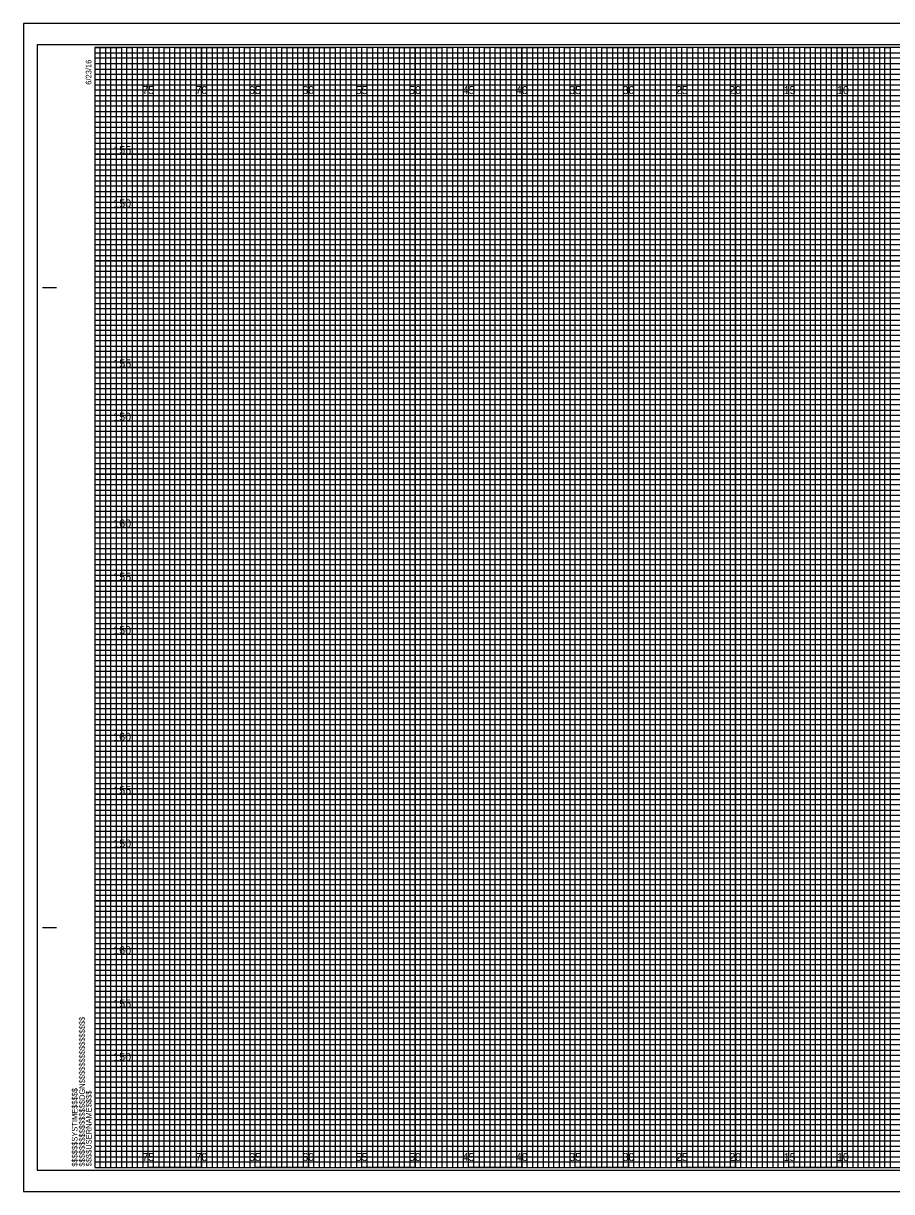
# Model space of a CAD drawing. Extents: x -7 to 162, y 108 to 217.
# Drawn here: x -6.7 to 74.6, y 107.7 to 217.2 of the extents above; entities that cross this region are included whole.
import ezdxf

# ---------------------------------------------------------------- set-up
doc = ezdxf.new("R2010")
doc.units = 0
for name, color, linetype in [('Exist CMT Pavement', 7, 'Continuous'), ('Prop CMT Pvmt Course 1 Wedge', 7, 'Continuous'), ('Prop CMT Pvmt Course 2 Wedge', 7, 'Continuous'), ('Prop CMT Pvmt Course 3 Wedge', 7, 'Continuous'), ('Prop CMT Pvmt Wedge Surface 1', 7, 'Continuous'), ('Prop CMT Pvmt Wedge Surface 2', 7, 'Continuous'), ('Prop CMT Shear Line', 7, 'Continuous'), ('Prop VPT Ditch Grade Left Label', 7, 'Continuous'), ('Prop XS Elevation Labels', 7, 'Continuous'), ('Scratch_Level_3', 7, 'Continuous'), ('Scratch_Level_5', 7, 'Continuous')]:
    doc.layers.add(name, color=color, linetype=linetype)

msp = doc.modelspace()

# ---------------------------------------------------------------- linework, layer by layer
at = {"layer": 'Exist CMT Pavement'}
for p, q in [((0, 214.5), (130, 214.5)), ((130, 213.99), (0, 213.99)), ((0, 213.99), (0, 213.5)), ((0, 213.5), (130, 213.5)), ((130, 212.94), (0, 212.94)), ((0, 212.94), (0, 212)), ((0, 212), (160, 212))]:
    msp.add_line(p, q, dxfattribs=at)
for points in [[(0, 211.5), (135, 211.5), (160, 211.5), (160, 211), (0, 211)], [(0, 210.5), (160, 210.5), (160, 209.5), (0, 209.5)], [(0, 209), (160, 209), (160, 208.5), (0, 208.49)], [(0, 208), (160, 208), (160, 207), (0, 207)], [(0, 206.5), (160, 206.5), (160, 206), (0, 206)], [(0, 205.5), (160, 205.5), (160, 204.5), (0, 204.5)], [(0, 204), (160, 204), (160, 203.5), (0, 203.5)], [(0, 203), (160, 203), (160, 202), (0, 202)], [(0, 201.5), (160, 201.5), (160, 201), (0, 201)], [(0, 200.5), (160, 200.5), (160, 199.5), (0, 199.5)], [(0, 199), (160, 199), (160, 198.5), (0, 198.5)], [(0, 198), (160, 198), (160, 196.97), (160, 196.5), (160, 196), (0, 196)], [(0, 197), (160, 197), (160, 196.5), (0, 196.5)], [(0, 195.5), (160, 195.5), (160, 194.5), (0, 194.52)], [(0, 194.52), (160, 194.5), (160, 194), (0, 194)], [(0, 193.5), (160, 193.5), (160, 193), (0, 193)], [(0, 192), (160, 192), (160, 191.5), (0, 191.5)], [(0, 191), (160, 191), (160, 190.5), (0, 190.5)], [(-0.04, 189.44), (160, 189.44), (160, 188.94), (-0.04, 188.94)], [(0, 188.5), (160, 188.5), (160, 188), (0, 188)], [(0, 187), (160, 187), (160, 186.5), (0, 186.5)], [(0, 186), (160, 186), (160, 185.5), (0, 185.5)], [(0, 184.5), (160, 184.5), (160, 184), (0, 184)], [(0, 183.5), (160, 183.5), (160, 183), (0, 183)], [(0, 182), (160, 182), (160, 181.5), (0, 181.5)], [(0, 181), (160, 181), (160, 180.5), (0, 180.5)], [(0, 179.5), (160, 179.5), (160, 178.99), (0, 179)], [(0, 178.5), (160, 178.5), (160, 178), (0, 178)], [(0, 177), (160, 177), (160, 176.5), (0, 176.5)], [(0, 176), (160, 176), (160, 175.5), (0, 175.5)], [(0, 174.5), (160, 174.5), (160, 174), (0, 174)], [(0, 173.5), (160, 173.5), (160, 173), (0, 173)], [(0, 172), (160, 172), (160, 171.5), (0, 171.5)], [(0, 171), (160, 171), (160, 170.5), (0, 170.5)], [(0, 169.5), (160, 169.5), (160, 169), (0, 169)], [(0, 168.5), (160.03, 168.46), (160, 168), (0, 168)], [(0, 167), (160, 167), (160, 166.5), (0, 166.5)], [(0, 166), (160, 166), (160, 165.5), (0, 165.5)], [(0, 164.5), (160, 164.5), (160, 164), (0, 164)], [(0, 163.5), (160, 163.5), (160, 163), (0, 163)], [(0, 162), (160, 162), (160, 161.5), (0, 161.5)], [(0, 161), (160, 161), (160, 160.5), (0, 160.5)], [(0, 159.5), (160, 159.5), (160, 159), (0, 159)], [(0, 158.5), (160, 158.5), (160, 158), (0, 158)], [(0, 157), (160, 157), (160, 156.5), (0, 156.5)], [(0, 156), (160, 156), (160, 155.5), (0, 155.5)], [(0, 154.5), (160, 154.5), (160, 154), (0, 154)], [(0, 153.5), (160, 153.5), (160, 153), (0, 153)], [(0, 152), (160, 152), (160, 151.5), (0, 151.5)], [(0, 151), (160, 151), (160, 150.5), (0, 150.5)], [(0, 149.5), (160, 149.5), (160, 148.99), (0, 149)], [(0, 148.5), (160, 148.5), (160, 148), (0, 148)], [(0, 147), (160, 147), (160, 146.5), (0, 146.5)], [(0, 146), (160, 146), (160, 145.5), (0, 145.5)], [(0, 144.5), (160, 144.5), (160, 144), (0, 144)], [(0, 143.5), (160, 143.5), (160, 143), (0, 143)], [(0, 142), (160, 142), (160, 141.5), (0, 141.5)], [(0, 141), (160, 141), (160, 140.5), (0, 140.5)], [(0, 139.5), (160, 139.5), (160, 139), (0, 139)], [(0, 138.5), (160.03, 138.46), (160, 138), (0, 138)], [(0, 137), (160, 137), (160, 136.5), (0, 136.5)], [(0, 136), (160, 136), (160, 135.5), (0, 135.5)], [(0, 134.5), (160, 134.5), (160, 134), (0, 134)], [(0, 133.5), (160, 133.5), (160, 133), (0, 133)], [(0, 132), (160, 132), (160, 131.5), (0, 131.5)], [(0, 131), (160, 131), (160, 130.5), (0, 130.5)], [(0, 129.5), (160, 129.5), (160, 129), (0, 129)], [(0, 128.5), (160, 128.5), (160, 128), (0, 128)], [(0, 127), (160, 127), (160, 126.5), (0, 126.5)], [(0, 126), (160, 126), (160, 125.5), (0, 125.5)], [(0, 124.5), (160, 124.5), (160, 124), (0, 124)], [(0, 123.5), (160, 123.5), (160, 123), (0, 123)], [(0, 122), (160, 122), (160, 121.5), (0, 121.5)], [(0, 121), (160, 121), (160, 120.5), (0, 120.5)], [(0, 119.5), (160, 119.5), (160, 119), (0, 119)], [(0, 118.5), (160, 118.5), (160, 118), (0, 118)], [(0, 117), (160, 117), (160, 116.5), (0, 116.5)], [(0, 116), (160, 116), (160, 115.5), (0, 115.5)], [(0, 114.5), (160, 114.5), (160, 114), (0, 114)], [(0, 113.5), (160, 113.5), (160, 113), (0, 113)], [(0, 112), (160, 112), (160, 111.5), (0, 111.5)], [(0, 111), (160, 111), (160, 110.5), (0, 110.5)]]:
    msp.add_lwpolyline(points, dxfattribs=at)
at = {"layer": 'Prop CMT Pvmt Course 2 Wedge'}
for p, q in [((5, 215), (0, 215)), ((5, 110), (5, 215)), ((15, 215), (10, 215)), ((10, 215), (10, 110)), ((15, 110), (15, 215)), ((25, 215), (20, 215)), ((20, 215), (20, 110)), ((25, 110), (25, 215)), ((35, 215), (30, 215)), ((30, 215), (30, 110)), ((35, 110), (35, 215)), ((45, 215), (40, 215)), ((40, 215), (40, 110)), ((45, 110), (45, 215)), ((55, 215), (50, 215)), ((50, 215), (50, 110)), ((55, 110), (55, 215)), ((65, 215), (60, 215)), ((60, 215), (60, 110)), ((65, 110), (65, 215)), ((75, 215), (70, 215)), ((70, 215), (70, 110)), ((10, 110), (5, 110)), ((20, 110), (15, 110)), ((30, 110), (25, 110)), ((40, 110), (35, 110)), ((50, 110), (45, 110)), ((60, 110), (55, 110)), ((70, 110), (65, 110))]:
    msp.add_line(p, q, dxfattribs=at)
for points in [[(0, 210), (160, 210), (160, 205), (0, 205)], [(0, 200), (160, 200), (160, 195), (0, 195)], [(0, 190), (160, 190), (160, 185), (0, 185)], [(0, 180), (160, 180), (160, 175), (0, 175)], [(0, 170), (160, 170), (160, 165), (0, 165)], [(0, 160), (160, 160), (160, 155), (0, 155)], [(0, 150), (160, 150), (160, 145), (0, 145)], [(0, 140), (160, 140), (160, 135), (0, 135)], [(0, 130), (160, 130), (160, 125), (0, 125)], [(0, 120), (160, 120), (160, 115), (0, 115)]]:
    msp.add_lwpolyline(points, dxfattribs=at)
at = {"layer": 'Prop CMT Pvmt Course 3 Wedge'}
for points in [[(0, 215), (2.5, 215), (2.5, 110), (7.5, 110), (7.5, 215), (12.5, 215), (12.5, 110), (17.5, 110), (17.5, 215), (22.5, 215), (22.5, 110), (27.5, 110), (27.5, 215), (32.5, 215), (32.5, 110), (37.5, 110), (37.5, 215), (42.5, 215), (42.5, 110), (47.5, 110), (47.5, 215), (52.5, 215), (52.5, 110), (57.5, 110), (57.5, 215), (62.5, 215), (62.5, 110), (67.5, 110), (67.5, 215), (72.5, 215), (72.5, 110), (77.5, 110)], [(0, 212.5), (137.5, 212.5)], [(0, 202.5), (160, 202.5), (160, 207.5), (0, 207.5)], [(0, 192.5), (160, 192.5), (160, 197.5), (0, 197.5)], [(0, 182.5), (160, 182.5), (160, 187.5), (0, 187.5)], [(0, 172.5), (160, 172.5), (160, 177.5), (0, 177.5)], [(0, 162.5), (160, 162.5), (160, 167.5), (0, 167.5)], [(0, 152.5), (160, 152.5), (160, 157.5), (0, 157.5)], [(0, 142.5), (160, 142.5), (160, 147.5), (0, 147.5)], [(0, 132.5), (160, 132.5), (160, 137.5), (0, 137.5)], [(0, 122.5), (160, 122.5), (160, 127.5), (0, 127.5)], [(0, 112.5), (160, 112.5), (160, 117.5), (0, 117.5)]]:
    msp.add_lwpolyline(points, dxfattribs=at)
at = {"layer": 'Prop CMT Pvmt Wedge Surface 1'}
for p, q in [((-4.9, 192.5), (-3.65, 192.5)), ((-4.85, 192.5), (-3.6, 192.5)), ((-4.9, 132.5), (-3.65, 132.5)), ((-4.85, 132.5), (-3.6, 132.5)), ((0, 110), (0, 110)), ((0, 110), (0, 110)), ((0, 110), (0, 110)), ((0, 110), (0, 110)), ((0, 110), (0, 110)), ((0, 110), (0, 110)), ((0, 110), (0, 110))]:
    msp.add_line(p, q, dxfattribs=at)
msp.add_lwpolyline([(160, 215), (0, 215), (0, 110), (160, 110)], close=True, dxfattribs=at)
at = {"layer": 'Prop CMT Pvmt Wedge Surface 2'}
for points in [[(0, 110), (0.5, 110), (0.5, 215), (1, 215), (1, 110)], [(1, 110), (1.5, 110), (1.5, 215), (2, 215), (2, 110)], [(2.5, 110), (3, 110), (3, 215), (3.5, 215), (3.5, 110)], [(3.5, 110), (4, 110), (4, 215), (4.5, 215), (4.5, 110)], [(5, 110), (5.5, 110), (5.5, 215), (6, 215), (6, 110)], [(6, 110), (6.5, 110), (6.5, 215), (7, 215), (7, 110)], [(7.5, 110), (8, 110), (8, 215), (8.5, 215), (8.5, 110)], [(8.5, 110), (9, 110), (9, 215), (9.5, 215), (9.5, 110)], [(10, 110), (10.5, 110), (10.5, 215), (11, 215), (11, 110)], [(11, 110), (11.5, 110), (11.5, 215), (12, 215), (12, 110)], [(12.5, 110), (13, 110), (13, 215), (13.5, 215), (13.5, 110)], [(13.5, 110), (14, 110), (14, 215), (14.5, 215), (14.5, 110)], [(15, 110), (15.5, 110), (15.5, 215), (16, 215), (16, 110)], [(16, 110), (16.5, 110), (16.5, 215), (17, 215), (17, 110)], [(17.5, 110), (18, 110), (18, 215), (18.5, 215), (18.5, 110)], [(18.5, 110), (19, 110), (19, 215), (19.5, 215), (19.5, 110)], [(20, 110), (20.5, 110), (20.5, 215), (21, 215), (21, 110)], [(21, 110), (21.5, 110), (21.5, 215), (22, 215), (22, 110)], [(22.5, 110), (23, 110), (23, 215), (23.5, 215), (23.5, 110)], [(23.5, 110), (24, 110), (24, 215), (24.5, 215), (24.5, 110)], [(25, 110), (25.5, 110), (25.5, 215), (26, 215), (26, 110)], [(26, 110), (26.5, 110), (26.5, 215), (27, 215), (27, 110)], [(27.5, 110), (28, 110), (28, 215), (28.5, 215), (28.5, 110)], [(28.5, 110), (29, 110), (29, 215), (29.5, 215), (29.5, 110)], [(30, 110), (30.5, 110), (30.5, 215), (31, 215), (31, 110)], [(31, 110), (31.5, 110), (31.5, 215), (32, 215), (32, 110)], [(32.5, 110), (33, 110), (33, 215), (33.5, 215), (33.5, 110)], [(33.5, 110), (34, 110), (34, 215), (34.5, 215), (34.5, 110)], [(35, 110), (35.5, 110), (35.5, 215), (36, 215), (36, 110)], [(36, 110), (36.5, 110), (36.5, 215), (37, 215), (37, 110)], [(37.5, 110), (38, 110), (38, 215), (38.5, 215), (38.5, 110)], [(38.5, 110), (39, 110), (39, 215), (39.5, 215), (39.5, 110)], [(40, 110), (40.5, 110), (40.5, 215), (41, 215), (41, 110)], [(41, 110), (41.5, 110), (41.5, 215), (42, 215), (42, 110)], [(42.5, 110), (43, 110), (43, 215), (43.5, 215), (43.5, 110)], [(43.5, 110), (44, 110), (44, 215), (44.5, 215), (44.5, 110)], [(45, 110), (45.5, 110), (45.5, 215), (46, 215), (46, 110)], [(46, 110), (46.5, 110), (46.5, 215), (47, 215), (47, 110)], [(47.5, 110), (48, 110), (48, 215), (48.5, 215), (48.5, 110)], [(48.5, 110), (49, 110), (49, 215), (49.5, 215), (49.5, 110)], [(50, 110), (50.5, 110), (50.5, 215), (51, 215), (51, 110)], [(51, 110), (51.5, 110), (51.5, 215), (52, 215), (52, 110)], [(52.5, 110), (53, 110), (53, 215), (53.5, 215), (53.5, 110)], [(53.5, 110), (54, 110), (54, 215), (54.5, 215), (54.5, 110)], [(55, 110), (55.5, 110), (55.5, 215), (56, 215), (56, 110)], [(56, 110), (56.5, 110), (56.5, 215), (57, 215), (57, 110)], [(57.5, 110), (58, 110), (58, 215), (58.5, 215), (58.5, 110)], [(58.5, 110), (59, 110), (59, 215), (59.5, 215), (59.5, 110)], [(60, 110), (60.5, 110), (60.5, 215), (61, 215), (61, 110)], [(61, 110), (61.5, 110), (61.5, 215), (62, 215), (62, 110)], [(62.5, 110), (63, 110), (63, 215), (63.5, 215), (63.5, 110)], [(63.5, 110), (64, 110), (64, 215), (64.5, 215), (64.5, 110)], [(65, 110), (65.5, 110), (65.5, 215), (66, 215), (66, 110)], [(66, 110), (66.5, 110), (66.5, 215), (67, 215), (67, 110)], [(67.5, 110), (68, 110), (68, 215), (68.5, 215), (68.5, 110)], [(68.5, 110), (69, 110), (69, 215), (69.5, 215), (69.5, 110)], [(70, 110), (70.5, 110), (70.5, 215), (71, 215), (71, 110)], [(71, 110), (71.5, 110), (71.5, 215), (72, 215), (72, 110)], [(72.5, 110), (73, 110), (73, 215), (73.5, 215), (73.5, 110)], [(73.5, 110), (74, 110), (74, 215), (74.5, 215), (74.5, 110)]]:
    msp.add_lwpolyline(points, dxfattribs=at)
at = {"layer": 'Prop CMT Shear Line'}
for p, q in [((161.65, 217.25), (-6.7, 217.25)), ((-6.7, 217.25), (-6.7, 107.75)), ((-6.7, 107.75), (161.65, 107.75))]:
    msp.add_line(p, q, dxfattribs=at)
at = {"layer": 'Prop VPT Ditch Grade Left Label'}
for p, q in [((5, 110), (5, 215)), ((10, 110), (10, 215)), ((15, 110), (15, 215)), ((20, 110), (20, 215)), ((25, 110), (25, 215)), ((30, 110), (30, 215)), ((35, 110), (35, 215)), ((40, 110), (40, 215)), ((45, 110), (45, 215)), ((50, 110), (50, 215)), ((55, 110), (55, 215)), ((60, 110), (60, 215)), ((65, 110), (65, 215)), ((70, 110), (70, 215)), ((0, 210), (160, 210)), ((0, 205), (160, 205)), ((0, 200), (160, 200)), ((0, 195), (160, 195)), ((0, 190), (160, 190)), ((0, 185), (160, 185)), ((0, 180), (160, 180)), ((0, 175), (160, 175)), ((0, 170), (160, 170)), ((0, 165), (160, 165)), ((0, 160), (160, 160)), ((0, 155), (160, 155)), ((0, 150), (160, 150)), ((0, 145), (160, 145)), ((0, 140), (160, 140)), ((0, 135), (160, 135)), ((0, 130), (160, 130)), ((0, 125), (160, 125)), ((0, 120), (160, 120)), ((0, 115), (160, 115))]:
    msp.add_line(p, q, dxfattribs=at)
at = {"layer": 'Scratch_Level_3'}
msp.add_lwpolyline([(-5.4, 109.75), (161.2, 109.75), (161.2, 215.25), (-5.4, 215.25)], close=True, dxfattribs=at)
at = {"layer": 'Scratch_Level_5'}
msp.add_lwpolyline([(-6.7, 107.75), (161.65, 107.75), (161.65, 217.25), (-6.7, 217.25)], close=True, dxfattribs=at)

# ---------------------------------------------------------------- texts
at = {"layer": 'Prop CMT Pvmt Course 1 Wedge'}
for s, p in [('75', (4.44, 210.62)), ('70', (9.43, 210.62)), ('65', (14.44, 210.62)), ('60', (19.43, 210.62)), ('55', (24.44, 210.62)), ('50', (29.43, 210.62)), ('45', (34.44, 210.62)), ('40', (39.43, 210.62)), ('35', (44.44, 210.62)), ('30', (49.43, 210.62)), ('25', (54.44, 210.62)), ('20', (59.43, 210.62)), ('15', (64.53, 210.62)), ('10', (69.52, 210.62)), ('75', (4.44, 110.62)), ('70', (9.43, 110.62)), ('65', (14.44, 110.62)), ('60', (19.43, 110.62)), ('55', (24.44, 110.62)), ('50', (29.43, 110.62)), ('45', (34.44, 110.62)), ('40', (39.43, 110.62)), ('35', (44.44, 110.62)), ('30', (49.43, 110.62)), ('25', (54.44, 110.62)), ('20', (59.43, 110.62)), ('15', (64.53, 110.62)), ('10', (69.52, 110.62))]:
    msp.add_text(s, height=0.75, dxfattribs=at).set_placement(p)
at = {"layer": 'Prop CMT Pvmt Wedge Surface 1'}
for s, p in [('6/23/16', (-0.33, 211.5)), ('$$$$$$$$$$$$$$$$DGN$$$$$$$$$$$$$$$$', (-0.94, 110.09)), ('$$$$$$SYSTIME$$$$$', (-1.63, 110.09)), ('$$$$USERNAME$$$$', (-0.31, 110.12))]:
    msp.add_text(s, height=0.525, rotation=90, dxfattribs=at).set_placement(p)
at = {"layer": 'Prop XS Elevation Labels'}
for s, p in [('155', (1.73, 205)), ('150', (1.72, 200)), ('155', (1.73, 185)), ('150', (1.72, 180)), ('160', (1.72, 170)), ('155', (1.73, 165)), ('150', (1.72, 160)), ('160', (1.72, 150)), ('155', (1.73, 145)), ('150', (1.72, 140)), ('160', (1.72, 130)), ('155', (1.73, 125)), ('150', (1.72, 120))]:
    msp.add_text(s, height=0.75, dxfattribs=at).set_placement(p)

doc.saveas('drawing.dxf')
